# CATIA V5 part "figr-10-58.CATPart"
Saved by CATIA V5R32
Part number: Part1
Bounding box of the stored display mesh (mm): x -322.306 to 0, y -118.205 to 88.531, z 0 to 101.949
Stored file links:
  D:\PROJECTS\Project 2022\CATIA V5 6R 2022\Resources\Part Files\c10_catia_v5_6r2022_prt\c10_catia_v5_6r2022_prt\figr-10-58.CATPart
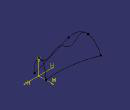
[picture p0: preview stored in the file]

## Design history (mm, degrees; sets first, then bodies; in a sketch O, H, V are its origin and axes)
Set1
  Curve1: Elements (Sketch2.P2; vertex of Sketch1; Sketch3.P2)
Body1 (main body)
  Sketch1 on zx-plane, origin (0, 0, 0), H (-1, 0, 0), V (0, 0, 1)
    spline S1 through (0, 96.336) (70.1946, 72.4244) (144.1119, 96.336) (203.5098, 63.985) (253.668, 92.1163) (322.3056, 72.4244)
    point P1 (0, 96.336)
    coincidence: P1 V
  Sketch2 on xy-plane, origin (0, 0, 0), H (1, 0, 0), V (0, 1, 0)
    point P1 (0, 47.0553)
    point P2 (-315.9706, 88.5306)
    arc A1 centre (-78.7604, 671.3501) radius 629.2433 from (0, 47.0553) to (-315.9706, 88.5306) cw
    coincidence: P1 V
  Sketch3 on xy-plane, origin (0, 0, 0), H (1, 0, 0), V (0, 1, 0)
    line L1 (0, -26.5991) -> (-311.8959, -118.2048)
    point P1 (0, -26.5991)
    point P2 (-311.8959, -118.2048)
    coincidence: P1 V
  Sketch4 on yz-plane, origin (0, 0, 0), H (0, 1, 0), V (0, 0, 1)
    point P1 (-26.5991, 0)
    point P2 (0, 58.544)
    point P3 (47.0553, 0)
    reference projected point E1 (47.0553, 0) from vertex of Sketch2
    reference projected point E2 (-26.5991, 0) from vertex of Sketch3
    spline S1 through (-26.5991, 0) (-29.9268, 35.6209) (0, 96.336) (47.0553, 0)
    reference projected point E3 (0, 96.336) from vertex of Sketch1
    point P4 (-26.5991, 0)
    point P5 (0, 96.336)
    point P6 (47.0553, 0)
    coincidence: P1 H, P3 H, E1 P3, P1 E2, P4 P1, P5 V, P6 P3, E3 S1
